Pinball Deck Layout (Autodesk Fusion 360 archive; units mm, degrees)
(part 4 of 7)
sketch "Round for Bumper" plane through (0, 0, 0) normal (0, 0, 1) x axis (1, 0, 0)
  line L1 (-43.2741, 196.0353) -> (-42.4787, 196.3248)
  line L2 (-43.527, 195.4929) -> (-43.2741, 196.0353)
  line L3 (-42.9846, 195.2399) -> (-43.527, 195.4929)
  line L4 (-42.1892, 195.5294) -> (-42.9846, 195.2399)
  line L5 (-43.0928, 194.2998) -> (-43.2375, 194.6975)
  line L6 (-43.1652, 194.4987) -> (-43.0928, 194.2998)
  line L7 (-41.9721, 194.9329) -> (-43.1652, 194.4987)
  line L8 (-42.2433, 195.0594) -> (-41.9721, 194.9329)
  line L9 (-42.6768, 193.7757) -> (-42.8757, 193.7033)
  line L10 (-42.6045, 193.5769) -> (-42.6768, 193.7757)
  line L11 (-42.8033, 193.5045) -> (-42.6045, 193.5769)
  line L12 (-42.8757, 193.7033) -> (-42.8033, 193.5045)
  line L13 (-41.2484, 192.9445) -> (-41.5196, 193.071)
  line L14 (-41.1037, 192.5469) -> (-41.2484, 192.9445)
  line L15 (-41.2302, 192.2757) -> (-41.1037, 192.5469)
  line L16 (-42.0255, 191.9862) -> (-41.2302, 192.2757)
  line L17 (-42.2967, 192.1126) -> (-42.0255, 191.9862)
  line L18 (-42.4414, 192.5103) -> (-42.2967, 192.1126)
  line L19 (-42.315, 192.7815) -> (-42.4414, 192.5103)
  line L20 (-41.5196, 193.071) -> (-42.315, 192.7815)
  line L21 (-40.5598, 196.8205) -> (-40.6863, 196.5493)
  line L22 (-40.7046, 197.2181) -> (-40.5598, 196.8205)
  line L23 (-40.9758, 197.3446) -> (-40.7046, 197.2181)
  line L24 (-41.7711, 197.0551) -> (-40.9758, 197.3446)
  line L25 (-41.8976, 196.7839) -> (-41.7711, 197.0551)
  line L26 (-41.7528, 196.3862) -> (-41.8976, 196.7839)
  line L27 (-41.4816, 196.2598) -> (-41.7528, 196.3862)
  line L28 (-41.391, 195.3921) -> (-41.5357, 195.7897)
  line L29 (-41.4634, 195.5909) -> (-41.391, 195.3921)
  line L30 (-40.668, 195.8804) -> (-41.4634, 195.5909)
  line L31 (-40.7404, 196.0792) -> (-40.668, 195.8804)
  line L32 (-41.1739, 194.7955) -> (-40.3785, 195.085)
  line L33 (-40.7762, 194.9403) -> (-41.1739, 194.7955)
  line L34 (-40.505, 194.8138) -> (-40.7762, 194.9403)
  line L35 (-40.2338, 194.6873) -> (-40.505, 194.8138)
  line L36 (-40.1614, 194.4885) -> (-40.2338, 194.6873)
  line L37 (-39.8719, 193.6932) -> (-39.6548, 193.0967)
  line L38 (-40.1431, 193.8196) -> (-39.8719, 193.6932)
  line L39 (-40.5408, 193.6749) -> (-40.1431, 193.8196)
  line L40 (-40.6673, 193.4037) -> (-40.5408, 193.6749)
  line L41 (-40.4502, 192.8072) -> (-40.6673, 193.4037)
  line L42 (-40.1607, 192.0118) -> (-40.3054, 192.4095)
  line L43 (-40.2331, 192.2107) -> (-40.1607, 192.0118)
  line L44 (-39.04, 192.6449) -> (-40.2331, 192.2107)
  line L45 (-39.1124, 192.8437) -> (-39.04, 192.6449)
  line L46 (-39.8712, 191.2165) -> (-39.7265, 190.8188)
  line L47 (-39.7447, 191.4877) -> (-39.8712, 191.2165)
  line L48 (-39.3471, 191.6324) -> (-39.7447, 191.4877)
  line L49 (-39.0758, 191.506) -> (-39.3471, 191.6324)
  line L50 (-38.9311, 191.1083) -> (-39.0758, 191.506)
  line L51 (-39.0576, 190.8371) -> (-38.9311, 191.1083)
  line L52 (-39.2564, 190.7647) -> (-39.0576, 190.8371)
  line L53 (-39.5459, 191.5601) -> (-39.2564, 190.7647)
  line L54 (-39.0751, 189.0293) -> (-37.8821, 189.4635)
  line L55 (-38.7856, 188.2339) -> (-39.0751, 189.0293)
  line L56 (-37.4479, 188.2705) -> (-37.1584, 187.4751)
  line L57 (-38.6409, 187.8362) -> (-37.4479, 188.2705)
  line L58 (-38.3514, 187.0409) -> (-38.6409, 187.8362)
  line L59 (-37.8996, 187.6557) -> (-38.0444, 188.0534)
  line L60 (-38.2067, 186.6432) -> (-37.0136, 187.0774)
  line L61 (-37.9896, 186.0467) -> (-38.2067, 186.6432)
  line L62 (-37.7184, 185.9202) -> (-37.9896, 186.0467)
  line L63 (-36.923, 186.2097) -> (-37.7184, 185.9202)
  line L64 (-36.7965, 186.4809) -> (-36.923, 186.2097)
  line L65 (-37.0136, 187.0774) -> (-36.7965, 186.4809)
  line L66 (-36.3623, 185.2879) -> (-36.4888, 185.0167)
  line L67 (-36.5071, 185.6856) -> (-36.3623, 185.2879)
  line L68 (-36.7783, 185.812) -> (-36.5071, 185.6856)
  line L69 (-36.9771, 185.7397) -> (-36.7783, 185.812)
  line L70 (-37.1036, 185.4685) -> (-36.9771, 185.7397)
  line L71 (-36.9588, 185.0708) -> (-37.1036, 185.4685)
  line L72 (-37.0853, 184.7996) -> (-36.9588, 185.0708)
  line L73 (-37.2841, 184.7272) -> (-37.0853, 184.7996)
  line L74 (-37.5553, 184.8537) -> (-37.2841, 184.7272)
  line L75 (-37.7001, 185.2514) -> (-37.5553, 184.8537)
  line L76 (-37.5736, 185.5226) -> (-37.7001, 185.2514)
  line L77 (-38.746, 198.1847) -> (-40.1776, 197.6636)
  line L78 (-38.4855, 197.4688) -> (-38.746, 198.1847)
  line L79 (-38.6372, 197.1434) -> (-38.4855, 197.4688)
  line L80 (-39.1144, 196.9697) -> (-38.6372, 197.1434)
  line L81 (-39.4399, 197.1215) -> (-39.1144, 196.9697)
  line L82 (-39.7004, 197.8373) -> (-39.4399, 197.1215)
  line L83 (-39.4829, 195.7548) -> (-39.6566, 196.232)
  line L84 (-39.5697, 195.9934) -> (-39.4829, 195.7548)
  line L85 (-38.6153, 196.3407) -> (-39.5697, 195.9934)
  line L86 (-38.7022, 196.5793) -> (-38.6153, 196.3407)
  line L87 (-38.2679, 195.3863) -> (-39.2223, 195.0389)
  line L88 (-38.0074, 194.6705) -> (-38.2679, 195.3863)
  line L89 (-38.1592, 194.3451) -> (-38.0074, 194.6705)
  line L90 (-38.875, 194.0845) -> (-38.1592, 194.3451)
  line L91 (-38.7013, 193.6073) -> (-37.2697, 194.1284)
  line L92 (-38.4407, 192.8915) -> (-38.7013, 193.6073)
  line L93 (-38.1153, 192.7397) -> (-38.4407, 192.8915)
  line L94 (-37.8767, 192.8266) -> (-38.1153, 192.7397)
  line L95 (-37.6381, 192.9134) -> (-37.8767, 192.8266)
  line L96 (-37.4863, 193.2389) -> (-37.6381, 192.9134)
  line L97 (-37.7469, 193.9547) -> (-37.4863, 193.2389)
  line L98 (-36.9653, 191.8072) -> (-37.1389, 192.2845)
  line L99 (-37.117, 191.4818) -> (-36.9653, 191.8072)
  line L100 (-37.8328, 191.2213) -> (-37.117, 191.4818)
  line L101 (-38.0934, 191.9371) -> (-37.8328, 191.2213)
  line L102 (-37.9416, 192.2625) -> (-38.0934, 191.9371)
  line L103 (-37.6162, 192.1108) -> (-37.9416, 192.2625)
  line L104 (-37.3556, 191.395) -> (-37.6162, 192.1108)
  line L105 (-37.4854, 190.2668) -> (-37.6591, 190.7441)
  line L106 (-37.5723, 190.5054) -> (-37.4854, 190.2668)
  line L107 (-36.1407, 191.0265) -> (-37.5723, 190.5054)
  line L108 (-36.2275, 191.2651) -> (-36.1407, 191.0265)
  line L109 (-37.0512, 189.0738) -> (-37.2249, 189.551)
  line L110 (-37.1381, 189.3124) -> (-37.0512, 189.0738)
  line L111 (-35.7064, 189.8335) -> (-37.1381, 189.3124)
  line L112 (-35.7933, 190.0721) -> (-35.7064, 189.8335)
  line L113 (-36.6059, 198.5102) -> (-36.7576, 198.1848)
  line L114 (-36.7796, 198.9875) -> (-36.6059, 198.5102)
  line L115 (-37.105, 199.1392) -> (-36.7796, 198.9875)
  line L116 (-37.3436, 199.0524) -> (-37.105, 199.1392)
  line L117 (-37.4954, 198.7269) -> (-37.3436, 199.0524)
  line L118 (-37.3217, 198.2497) -> (-37.4954, 198.7269)
  line L119 (-37.4735, 197.9243) -> (-37.3217, 198.2497)
  line L120 (-37.7121, 197.8374) -> (-37.4735, 197.9243)
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sketch "Sketch43" plane through (0, 0, 0) normal (0, 0, 1) x axis (1, 0, 0)
sketch "Speaker Grille" plane through (0, 0, 0) normal (0, 0, 1) x axis (1, 0, 0)
  circle C1 centre (2212.5, 1932.5) radius 45
  circle C2 centre (2212.5, 1932.5) radius 67.5
  circle C3 centre (2171.5, 1973.5) radius 6
  circle C4 centre (2253.5, 1973.5) radius 6
  circle C5 centre (2253.5, 1891.5) radius 6
  circle C6 centre (2171.5, 1891.5) radius 6
  circle C7 centre (2648.5, 1973.5) radius 6
  circle C8 centre (2566.5, 1973.5) radius 6
  circle C9 centre (2607.5, 1932.5) radius 45
  circle C10 centre (2607.5, 1932.5) radius 67.5
  circle C11 centre (2648.5, 1891.5) radius 6
  circle C12 centre (2566.5, 1891.5) radius 6
  point P2 (2212.5, 1932.5)
  point P3 (2212.5, 1932.5)
  point P5 (2171.5, 1973.5)
  point P6 (2171.5, 1973.5)
  coincident P2 P3
  concentric C1 C2
  coincident P5 P6
  concentric C9 C10
extrude "Extrude174" new body sketch "Speaker Grille" profile of C1 C2 C3 C4 C5 C6 along normal blind 8 bodies "Speaker Grille"
extrude "Extrude175" add sketch "Speaker Grille" profile of C3 C4 C5 C6 blind 3 from offset 5
extrude "Extrude176" add sketch "Speaker Grille" profile of C1 blind 3 from offset 5
sketch "Speaker Grille Holes" plane through (0, 0, 8) normal (0, 0, 1) x axis (-1, 0, 0)
  circle C1 centre (-2212.5, -1932.5) radius 67.5
  circle C2 centre (-2212.5, -1932.5) radius 4
  circle C3 centre (-2212.5, -1944.5) radius 4
  circle C4 centre (-2202.1077, -1938.5) radius 4
  circle C5 centre (-2202.1077, -1926.5) radius 4
  circle C6 centre (-2212.5, -1920.5) radius 4
  circle C7 centre (-2222.8923, -1926.5) radius 4
  circle C8 centre (-2222.8923, -1938.5) radius 4
  circle C9 centre (-2212.5, -1956.5) radius 4
  circle C10 centre (-2200.5, -1953.2846) radius 4
  circle C11 centre (-2191.7154, -1944.5) radius 4
  circle C12 centre (-2188.5, -1932.5) radius 4
  circle C13 centre (-2191.7154, -1920.5) radius 4
  circle C14 centre (-2200.5, -1911.7154) radius 4
  circle C15 centre (-2212.5, -1908.5) radius 4
  circle C16 centre (-2224.5, -1911.7154) radius 4
  circle C17 centre (-2233.2846, -1920.5) radius 4
  circle C18 centre (-2236.5, -1932.5) radius 4
  circle C19 centre (-2233.2846, -1944.5) radius 4
  circle C20 centre (-2224.5, -1953.2846) radius 4
  circle C21 centre (-2212.5, -1968.5) radius 4
  circle C22 centre (-2200.1873, -1966.3289) radius 4
  circle C23 centre (-2189.3596, -1960.0776) radius 4
  circle C24 centre (-2181.3231, -1950.5) radius 4
  circle C25 centre (-2177.0469, -1938.7513) radius 4
  circle C26 centre (-2177.0469, -1926.2487) radius 4
  circle C27 centre (-2181.3231, -1914.5) radius 4
  circle C28 centre (-2189.3596, -1904.9224) radius 4
  circle C29 centre (-2200.1873, -1898.6711) radius 4
  circle C30 centre (-2212.5, -1896.5) radius 4
  circle C31 centre (-2224.8127, -1898.6711) radius 4
  circle C32 centre (-2235.6404, -1904.9224) radius 4
  circle C33 centre (-2243.6769, -1914.5) radius 4
  circle C34 centre (-2247.9531, -1926.2487) radius 4
  circle C35 centre (-2247.9531, -1938.7513) radius 4
  circle C36 centre (-2243.6769, -1950.5) radius 4
  circle C37 centre (-2235.6404, -1960.0776) radius 4
  circle C38 centre (-2224.8127, -1966.3289) radius 4
  circle C39 centre (-2212.5, -1980.5) radius 4
  circle C40 centre (-2200.0767, -1978.8644) radius 4
  circle C41 centre (-2188.5, -1974.0692) radius 4
  circle C42 centre (-2170.9308, -1956.5) radius 4
  circle C43 centre (-2166.1356, -1944.9233) radius 4
  circle C44 centre (-2164.5, -1932.5) radius 4
  circle C45 centre (-2166.1356, -1920.0767) radius 4
  circle C46 centre (-2170.9308, -1908.5) radius 4
  circle C47 centre (-2188.5, -1890.9308) radius 4
  circle C48 centre (-2200.0767, -1886.1356) radius 4
  circle C49 centre (-2212.5, -1884.5) radius 4
  circle C50 centre (-2224.9233, -1886.1356) radius 4
  circle C51 centre (-2236.5, -1890.9308) radius 4
  circle C52 centre (-2254.0692, -1908.5) radius 4
  circle C53 centre (-2258.8644, -1920.0767) radius 4
  circle C54 centre (-2260.5, -1932.5) radius 4
  circle C55 centre (-2258.8644, -1944.9233) radius 4
  circle C56 centre (-2254.0692, -1956.5) radius 4
  circle C57 centre (-2236.5, -1974.0692) radius 4
  circle C58 centre (-2224.9233, -1978.8644) radius 4
  circle C59 centre (-2272.5, -1932.5) radius 5
  circle C60 centre (-2272.5, -1932.5) radius 2.4
  circle C61 centre (-2212.5, -1992.5) radius 2.4
  circle C62 centre (-2212.5, -1992.5) radius 5
  circle C63 centre (-2152.5, -1932.5) radius 2.4
  circle C64 centre (-2152.5, -1932.5) radius 5
  circle C65 centre (-2212.5, -1872.5) radius 2.4
  circle C66 centre (-2212.5, -1872.5) radius 5
  arc A1 centre (-2212.5, -1932.5) radius 53 clockwise from (-2161.3349, -1946.3252) to (-2198.8813, -1983.7204)
  arc A2 centre (-2212.5, -1932.5) radius 53 clockwise from (-2226.7387, -1983.5515) to (-2263.6765, -1946.2829)
  arc A3 centre (-2212.5, -1932.5) radius 53 clockwise from (-2198.8356, -1881.2918) to (-2161.4158, -1918.3788)
  arc A4 centre (-2212.5, -1932.5) radius 53 clockwise from (-2263.5966, -1918.424) to (-2226.2846, -1881.324)
  arc A5 centre (-2607.5, -1932.5) radius 53 clockwise from (-2658.5966, -1918.424) to (-2621.2846, -1881.324)
  arc A6 centre (-2607.5, -1932.5) radius 53 clockwise from (-2621.7387, -1983.5515) to (-2658.6765, -1946.2829)
  arc A7 centre (-2607.5, -1932.5) radius 53 clockwise from (-2556.3349, -1946.3252) to (-2593.8813, -1983.7204)
  arc A8 centre (-2607.5, -1932.5) radius 53 clockwise from (-2593.8356, -1881.2918) to (-2556.4158, -1918.3788)
  circle C67 centre (-2607.5, -1992.5) radius 5
  circle C68 centre (-2607.5, -1992.5) radius 2.4
  circle C69 centre (-2547.5, -1932.5) radius 2.4
  circle C70 centre (-2547.5, -1932.5) radius 5
  circle C71 centre (-2607.5, -1872.5) radius 2.4
  circle C72 centre (-2607.5, -1872.5) radius 5
  circle C73 centre (-2667.5, -1932.5) radius 2.4
  circle C74 centre (-2667.5, -1932.5) radius 5
  point P3 (-2212.5, -1932.5)
  point P68 (-2212.5, -1932.5)
  point P71 (-2212.5, -1932.5)
  point P74 (-2212.5, -1932.5)
  point P77 (-2212.5, -1932.5)
  point P80 (-2607.5, -1932.5)
  point P91 (-2607.5, -1932.5)
  concentric C1 C2
  concentric C59 C60
  coincident P3 P68
  coincident P3 P71
  coincident P3 P74
  coincident P68 P77
  coincident P80 P91
  dimension "d1064" radius A1 = 53
  dimension "d1065" radius A2 = 53
  dimension "d1070" radius A3 = 53
  dimension "d1071" radius A4 = 53
  dimension "d1114" radius A7 = 53
  dimension "d1115" radius A6 = 53
  dimension "d1116" radius A8 = 53
  dimension "d1117" radius A5 = 53
  dimension "d1048" C-Pattern1-Angle = 360
  dimension "d1050" C-Pattern2-Angle = 360
  dimension "d1052" C-Pattern3-Angle = 360
  dimension "d1054" C-Pattern4-Angle = 360
  dimension "d1058" C-Pattern5-Angle = 360
  dimension "d1066" Text1-Height = 10
  dimension "d1068" Text2-Height = 10
  dimension "d1072" Text3-Height = 10
  dimension "d1074" Text4-Height = 10
  dimension "d1106" Text5-Height = 10
  dimension "d1108" Text6-Height = 10
  dimension "d1110" Text7-Height = 10
  dimension "d1112" Text8-Height = 10
  dimension "d1119" C-Pattern6-Angle = 360
extrude "Extrude177" cut sketch "Speaker Grille Holes" profile of C2 C3 C4 C5 C6 C7 C8 C9 C10 C11 C12 C13 C14 C15 C16 C17 C18 C19 C20 C21 C22 C23 C24 C25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 against normal blind 20
extrude "Extrude178" cut sketch "Speaker Grille Holes" profile of C59 C60 C61 C62 C63 C64 C65 C66 against normal blind 5
chamfer "Chamfer16" distance 2
extrude "Extrude179" cut sketch "Speaker Grille Holes" against normal blind 0.6
extrude "Extrude184" new body sketch "Speaker Grille" profile of C7 C8 C9 C10 C11 C12 along normal blind 8 bodies "Speaker Grille Transistor"
extrude "Extrude185" add sketch "Speaker Grille" profile of C7 C8 C11 C12 blind 3 from offset 5
extrude "Extrude186" add sketch "BackBox" blind 5 from offset 3
extrude "Extrude187" cut sketch "Speaker Grille Holes" profile of C67 C68 C69 C70 C71 C72 C73 C74 against normal blind 5
extrude "Extrude188" cut sketch "Speaker Grille Holes" profile of C68 C69 C71 C73 against normal blind 20
extrude "Extrude189" cut sketch "Speaker Grille Holes" against normal blind 1
chamfer "Chamfer19" distance 1 distance 2
chamfer "Chamfer20" distance 2.5 distance 2.5
extrude "Extrude190" new body sketch "BackBox" along normal blind 1.6 bodies "Score and Player Stencil"
extrude "Extrude192" cut sketch "BackBox" along normal blind 10 bodies "Score and Player Stencil (1)", "Score and Player Stencil (2)", "Score and Player Stencil (3)", "Score and Player Stencil (4)", "Score and Player Stencil (5)"
extrude "Extrude193" add sketch "BackBox" along normal blind 1.6 bodies "Score and Player Stencil (1)", "Score and Player Stencil (2)", "Score and Player Stencil (3)", "Score and Player Stencil (4)", "Score and Player Stencil (5)"
sketch "TGM" plane through (0, 0, 26.8) normal (0, 0, 1) x axis (-1, 0, 0)
  curve K1 (-394.895, -516.8116) -> (-148.3535, -405.68)
  curve K2 (-362.2071, -513.1144) -> (-394.895, -516.8116)
  curve K3 (-392.0081, -507.9705) -> (-362.2071, -513.1144)
  curve K4 (-148.3535, -405.68) -> (-392.0081, -507.9705)
  line L1 (-352.5662, -523.8611) -> (-337.4773, -506.6421)
  line L2 (-356.4045, -516.3957) -> (-333.6368, -513.9907)
  line L3 (-352.3287, -506.4533) -> (-337.4165, -523.8216)
  line L4 (-345.8439, -503.8414) -> (-344.2038, -526.6773)
  curve K5 (-332.1435, -465.5509) -> (-304.0612, -510.3266)
  curve K6 (-304.0643, -503.1407) -> (-304.0581, -517.5125)
  curve K7 (-337.0307, -462.8305) -> (-327.2563, -468.2714)
  curve K8 (-328.9554, -457.7991) -> (-296.2565, -506.0172)
  curve K9 (-296.4222, -499.7021) -> (-296.0909, -512.3322)
  curve K10 (-334.5203, -454.8035) -> (-323.3905, -460.7946)
  curve K11 (-258.096, -394.5655) -> (-256.0404, -399.4978)
  curve K12 (-260.096, -394.5655) -> (-258.096, -394.5655)
  curve K13 (-262.096, -398.5655) -> (-260.096, -394.5655)
  curve K14 (-253.3716, -424.5776) -> (-256.0404, -399.4978)
  curve K15 (-265.3252, -424.1348) -> (-262.096, -398.5655)
  curve K16 (-286.9785, -407.2003) -> (-287.0771, -401.8711)
  curve K17 (-287.0771, -401.8711) -> (-282.6123, -402.0668)
  curve K18 (-282.6123, -402.0668) -> (-280.7826, -407.4713)
  curve K19 (-285.577, -415.4972) -> (-286.9785, -407.2003)
  curve K20 (-285.1672, -416.3355) -> (-285.9868, -414.6589)
  curve K21 (-332.7729, -448.7758) -> (-307.0356, -466.5006)
  curve K22 (-337.6691, -448.7758) -> (-332.7729, -448.7758)
  curve K23 (-336.4498, -444.5132) -> (-337.6691, -448.7758)
  curve K24 (-332, -445) -> (-336.4498, -444.5132)
  curve K25 (-298.7139, -460.4547) -> (-332, -445)
  curve K26 (-358.1837, -553.1493) -> (-358.3367, -550.0237)
  curve K27 (-359.8524, -555.6804) -> (-358.1837, -553.1493)
  curve K28 (-362.1811, -556.7129) -> (-359.8524, -555.6804)
  curve K29 (-365.399, -556.1322) -> (-362.1811, -556.7129)
  curve K30 (-367.832, -552.7289) -> (-365.399, -556.1322)
  curve K31 (-367.6403, -550.1846) -> (-367.832, -552.7289)
  curve K32 (-361.124, -547.211) -> (-358.4275, -549.8052)
  curve K33 (-354.3728, -543.4851) -> (-352.3173, -537.9664)
  curve K34 (-355.3735, -545.8038) -> (-353.3722, -541.1663)
  curve K35 (-358.3367, -550.0237) -> (-358.0882, -549.7182)
  curve K36 (-358.1133, -549.7497) -> (-358.063, -549.6868)
  curve K37 (-358.3624, -550.0547) -> (-358.3111, -549.9927)
  curve K38 (-358.6852, -542.9275) -> (-360.6858, -533.0429)
  curve K39 (-359.4374, -545.1004) -> (-357.9329, -540.7546)
  curve K40 (-365.2949, -547.4437) -> (-361.7976, -546.9968)
  curve K41 (-365.2949, -547.4437) -> (-367.6403, -550.1846)
  curve K42 (-338.3016, -546.0245) -> (-340.647, -548.7654)
  curve K43 (-331.3434, -548.6045) -> (-331.0949, -548.2991)
  curve K44 (-331.12, -548.3305) -> (-331.0697, -548.2676)
  curve K45 (-331.3691, -548.6355) -> (-331.3178, -548.5735)
  curve K46 (-335.1878, -555.2938) -> (-332.8591, -554.2612)
  curve K47 (-338.3016, -546.0245) -> (-334.8043, -545.5776)
  curve K48 (-327.3795, -542.0659) -> (-328.5961, -518.8979)
  curve K49 (-328.3802, -544.3846) -> (-326.3789, -539.7472)
  curve K50 (-332.8591, -554.2612) -> (-331.1904, -551.7302)
  curve K51 (-338.4057, -554.7131) -> (-335.1878, -555.2938)
  curve K52 (-334.1307, -545.7918) -> (-331.4342, -548.386)
  curve K53 (-331.6919, -541.5084) -> (-332.9354, -521.61)
  curve K54 (-332.4441, -543.6812) -> (-330.9396, -539.3355)
  curve K55 (-340.647, -548.7654) -> (-340.8386, -551.3097)
  curve K56 (-331.1904, -551.7302) -> (-331.3434, -548.6045)
  curve K57 (-340.8386, -551.3097) -> (-338.4057, -554.7131)
  curve K58 (-397.0602, -517.7138) -> (-144.7627, -402.5381)
  curve K59 (-368.4267, -511.372) -> (-397.0602, -517.7138)
  curve K60 (-395, -510) -> (-368.4267, -511.372)
  curve K61 (-144.7627, -402.5381) -> (-395, -510)
  curve K62 (-320.1132, -535.4659) -> (-160.9431, -423.5396)
  curve K63 (-277.7807, -414.9917) -> (-280.7826, -407.4713)
  curve K64 (-277.6152, -415.8774) -> (-277.9462, -414.1061)
  line L5 (-298.7139, -460.4547) -> (-307.0356, -466.5006)
  line L6 (-265.3252, -424.1348) -> (-253.3716, -424.5776)
  line L7 (-332.9354, -521.61) -> (-328.5961, -518.8979)
  line L8 (-243.986, -236.4878) -> (-243.986, -233.4398)
  line L9 (-284.626, -327.9278) -> (-284.626, -324.8798)
  line L10 (-264.306, -327.9278) -> (-264.306, -324.8798)
  line L11 (-243.986, -327.9278) -> (-243.986, -324.8798)
  line L12 (-223.666, -327.9278) -> (-223.666, -324.8798)
  line L13 (-203.346, -327.9278) -> (-203.346, -324.8798)
  line L14 (-233.826, -305.0678) -> (-233.826, -302.0198)
  line L15 (-213.506, -305.0678) -> (-213.506, -302.0198)
  line L16 (-264.306, -282.2078) -> (-264.306, -279.1598)
  line L17 (-243.986, -282.2078) -> (-243.986, -279.1598)
  line L18 (-223.666, -282.2078) -> (-223.666, -279.1598)
  line L19 (-254.146, -259.3478) -> (-254.146, -256.2998)
  line L20 (-233.826, -259.3478) -> (-233.826, -256.2998)
  line L21 (-274.466, -305.0678) -> (-274.466, -302.0198)
  line L22 (-254.146, -305.0678) -> (-254.146, -302.0198)
  line L23 (-223.666, -327.9278) -> (-223.666, -324.8798)
  line L24 (-203.346, -327.9278) -> (-203.346, -324.8798)
  line L25 (-264.306, -327.9278) -> (-264.306, -324.8798)
  line L26 (-264.306, -282.2078) -> (-264.306, -279.1598)
  line L27 (-284.626, -327.9278) -> (-284.626, -324.8798)
  line L28 (-243.986, -236.4878) -> (-243.986, -233.4398)
  line L29 (-254.146, -259.3478) -> (-254.146, -256.2998)
  line L30 (-254.146, -305.0678) -> (-254.146, -302.0198)
  line L31 (-233.826, -259.3478) -> (-233.826, -256.2998)
  line L32 (-274.466, -305.0678) -> (-274.466, -302.0198)
  line L33 (-223.666, -282.2078) -> (-223.666, -279.1598)
  line L34 (-243.986, -282.2078) -> (-243.986, -279.1598)
  line L35 (-213.506, -305.0678) -> (-213.506, -302.0198)
  line L36 (-233.826, -305.0678) -> (-233.826, -302.0198)
  line L37 (-243.986, -327.9278) -> (-243.986, -324.8798)
  line L38 (-223.666, -327.9278) -> (-223.666, -324.8798)
  line L39 (-203.346, -327.9278) -> (-203.346, -324.8798)
  line L40 (-264.306, -327.9278) -> (-264.306, -324.8798)
  line L41 (-264.306, -282.2078) -> (-264.306, -279.1598)
  line L42 (-284.626, -327.9278) -> (-284.626, -324.8798)
  line L43 (-243.986, -236.4878) -> (-243.986, -233.4398)
  line L44 (-254.146, -259.3478) -> (-254.146, -256.2998)
  line L45 (-254.146, -305.0678) -> (-254.146, -302.0198)
  line L46 (-233.826, -259.3478) -> (-233.826, -256.2998)
  line L47 (-274.466, -305.0678) -> (-274.466, -302.0198)
  line L48 (-223.666, -282.2078) -> (-223.666, -279.1598)
  line L49 (-243.986, -282.2078) -> (-243.986, -279.1598)
  line L50 (-213.506, -305.0678) -> (-213.506, -302.0198)
  line L51 (-233.826, -305.0678) -> (-233.826, -302.0198)
  line L52 (-243.986, -327.9278) -> (-243.986, -324.8798)
  circle C1 centre (-345.0137, -515.2586) radius 11.4474
  circle C2 centre (-362.9589, -551.8166) radius 4.9577
  circle C3 centre (-335.9656, -550.3974) radius 4.9577
  arc A1 centre (-243.986, -233.4398) radius 0.0635 clockwise from (-244.0495, -233.4398) to (-243.9225, -233.4398)
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  point P43 (-352.5662, -523.8611)
  point P44 (-356.4045, -516.3957)
  point P45 (-352.3287, -506.4533)
  point P46 (-337.4773, -506.6421)
  point P47 (-333.6368, -513.9907)
  point P48 (-337.4165, -523.8216)
  point P49 (-344.2038, -526.6773)
  point P50 (-345.8439, -503.8414)
  point P54 (-304.0612, -510.3266)
  point P55 (-332.1435, -465.5509)
  point P65 (-328.9554, -457.7991)
  point P66 (-296.2565, -506.0172)
  point P119 (-285.577, -415.4972)
  point P151 (-360.6858, -533.0429)
  point P153 (-352.3173, -537.9664)
  point P157 (-358.3367, -550.0237)
  point P163 (-358.1837, -553.1493)
  point P171 (-359.8524, -555.6804)
  point P179 (-362.1811, -556.7129)
  point P188 (-365.399, -556.1322)
  point P194 (-367.832, -552.7289)
  point P201 (-367.6403, -550.1846)
  point P202 (-358.4275, -549.8052)
  point P208 (-361.124, -547.211)
  point P209 (-354.3728, -543.4851)
  point P212 (-358.0882, -549.7182)
  point P217 (-358.6852, -542.9275)
  point P220 (-361.7976, -546.9968)
  point P227 (-365.2949, -547.4437)
  point P253 (-331.3434, -548.6045)
  point P282 (-331.1904, -551.7302)
  point P255 (-332.8591, -554.2612)
  point P305 (-335.1878, -555.2938)
  point P269 (-338.4057, -554.7131)
  point P251 (-340.8386, -551.3097)
  point P291 (-340.647, -548.7654)
  point P241 (-331.4342, -548.386)
  point P308 (-334.1307, -545.7918)
  point P234 (-327.3795, -542.0659)
  point P236 (-331.0949, -548.2991)
  point P284 (-331.6919, -541.5084)
  point P311 (-334.8043, -545.5776)
  point P312 (-338.3016, -546.0245)
  point P365 (-277.7807, -414.9917)
  point P95 (-262.9776, -416.5536)
  point P60 (-296.4222, -499.7021)
  point P68 (-296.4222, -499.7021)
  point P56 (-304.0581, -517.5125)
  point P362 (-304.0581, -517.5125)
  point P92 (-254.6103, -418.8368)
  coincident C1 P43
  coincident C1 P44
  coincident C1 P45
  coincident C1 P46
  coincident C1 P47
  coincident C1 P48
  coincident C1 P49
  coincident C1 P50
  coincident K1 P54
  coincident K4 P55
  midpoint P54 K6
  midpoint P55 K7
  coincident K4 P65
  coincident K1 P66
  midpoint P66 K9
  midpoint P65 K10
  coincident K4 P119
  midpoint P119 K20
  coincident K1 P151
  coincident K1 P153
  coincident C2 P157
  coincident C2 P163
  coincident C2 P171
  coincident C2 P179
  coincident C2 P188
  coincident C2 P194
  coincident C2 P201
  coincident C2 P202
  coincident C2 P208
  coincident K32 P209
  midpoint P209 K34
  coincident K32 P212
  midpoint P212 K36
  midpoint P157 K37
  coincident K32 P217
  midpoint P217 K39
  coincident C2 P220
  coincident C2 P227
  coincident P253 C3
  coincident P282 C3
  coincident P255 C3
  coincident P305 C3
  coincident P269 C3
  coincident P251 C3
  coincident P291 C3
  coincident P241 C3
  coincident P308 C3
  coincident P234 K52
  midpoint P234 K49
  coincident P236 K52
  midpoint P236 K44
  midpoint P253 K45
  coincident P284 K52
  midpoint P284 K54
  coincident P311 C3
  coincident P312 C3
  coincident K4 P365
  midpoint P365 K64
  coincident K4 P95
  coincident P60 P68
  coincident P56 P362
  coincident K4 P92
  dimension "d1224" diameter = 12
  dimension "d1225" diameter = 12
  dimension "d1139" Text1-Height = 8
  dimension "d1141" Text2-Height = 8
sketch "Sketch48" plane through (0, 0, 0) normal (0, 0, 1) x axis (1, 0, 0)
sketch "TGM Stencil Outline" plane through (0, 0, 26.8) normal (0, 0, 1) x axis (-1, 0, 0)
  line L1 (-335.7762, -328.4574) -> (-138.9755, -401.734)
  line L2 (-212.252, -598.5347) -> (-138.9755, -401.734)
  line L3 (-409.0528, -525.2582) -> (-212.252, -598.5347)
  line L4 (-409.0528, -525.2582) -> (-335.7762, -328.4574)
  line L5 (-235, -435) -> (-235, -375)
  line L6 (-300, -435) -> (-235, -435)
  line L7 (-300, -375) -> (-300, -435)
  line L8 (-235, -375) -> (-300, -375)
  line L9 (-290, -435) -> (-290, -513.0916)
  line L10 (-350, -435) -> (-290, -435)
  line L11 (-350, -513.0916) -> (-350, -435)
  line L12 (-290, -513.0916) -> (-350, -513.0916)
  line L13 (-380, -570) -> (-320, -570)
  line L14 (-380, -515) -> (-380, -570)
  line L15 (-320, -515) -> (-380, -515)
  line L16 (-320, -570) -> (-320, -515)
  line L17 (-360, -530) -> (-360, -500)
  line L18 (-330, -530) -> (-360, -530)
  line L19 (-330, -500) -> (-330, -530)
  line L20 (-360, -500) -> (-330, -500)
  point P11 (-290, -435)
  point P2 (-138.9755, -401.734)
  point P3 (-335.7762, -328.4574)
  point P4 (-212.252, -598.5347)
  point P5 (-409.0528, -525.2582)
  perpendicular L1 L2
  perpendicular L2 L3
  vertical L5
  perpendicular L5 L6
  perpendicular L6 L7
  perpendicular L5 L8
  coincident L6 P11
  perpendicular L6 L9
  perpendicular L9 L10
  perpendicular L10 L11
  perpendicular L9 L12
  parallel L12 L13
  perpendicular L12 L14
  perpendicular L14 L15
  perpendicular L13 L16
  vertical L17
  perpendicular L17 L18
  perpendicular L18 L19
  perpendicular L17 L20
  dimension "d1161" distance P2 P3 = 210
  dimension "d1162" distance P2 P4 = 210
  dimension "d1163" distance P4 P5 = 210
extrude "Extrude201" new body sketch "TGM Stencil Outline" profile of L1 L2 L3 L4 along normal blind 1.4 bodies "TGM Body Outline"
extrude "Extrude202" cut sketch "TGM" profile of K1 K2 K3 K4 K14 K15 K19 K21 K25 K38 K35 K42 K47 K48 K53 K58 K59 K60 K61 K63 along normal blind 10
extrude "Extrude203" new body sketch "TGM Stencil Outline" profile of L1 L2 L3 L4 along normal blind 1.4 bodies "TGM Main Body"
extrude "Extrude205" cut sketch "TGM" profile of K1 K2 K3 K4 C1 L1 L2 L3 L4 K5 K8 K14 K15 K21 K25 K48 K53 L5 L6 L7 along normal blind 10
extrude "Extrude206" new body sketch "TGM Stencil Outline" profile of L5 L6 L7 L8 L10 along normal blind 1.6 bodies "TGM Legs"
extrude "Extrude207" cut sketch "TGM" profile of K4 K11 K12 K13 K14 K15 K16 K17 K18 K19 K61 K63 L6 along normal blind 10
extrude "Extrude208" new body sketch "TGM Stencil Outline" profile of L6 L9 L10 L11 L12 L19 L20 along normal blind 1.6 bodies "TGM Arms"
extrude "Extrude209" cut sketch "TGM" profile of K4 K21 K22 K23 K24 K25 K61 L5 along normal blind 10
extrude "Extrude210" new body sketch "TGM Stencil Outline" profile of L6 L9 L10 L11 L12 L19 L20 along normal blind 1.4 bodies "TGM Necklace"
extrude "Extrude211" cut sketch "TGM" profile of K1 K4 K5 K8 along normal blind 10
extrude "Extrude212" new body sketch "TGM Stencil Outline" profile of L6 L9 L10 L11 L12 L19 L20 along normal blind 1.4 bodies "TGM Necklace 2"
extrude "Extrude213" cut sketch "TGM" along normal blind 10
extrude "Extrude214" new body sketch "TGM" + "TGM Stencil Outline" profile of S1:K1 S1:C1 S1:L1 S1:L2 S1:L3 S1:L4 S1:K38 S1:K35 S1:C2 S1:K26 S1:K27 S1:K28 S1:K29 S1:K30 S1:K31 S1:K32 S1:K40 S1:K41 S1:K42 S1:C3 S1:K43 S1:K46 S1:K47 S1:K48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 blind 1.4 bodies "TGM Ears"
extrude "Extrude215" cut sketch "TGM" profile of C2 K26 K27 K28 K29 K30 K31 K32 K40 K41 K42 C3 K46 K47 K50 K51 K52 K55 K56 K57 K58 along normal blind 10
extrude "Extrude216" new body sketch "TGM" + "TGM Stencil Outline" profile of S1:K1 S1:C1 S1:L1 S1:L2 S1:L3 S1:L4 S1:K38 S1:K35 S1:C2 S1:K26 S1:K27 S1:K28 S1:K29 S1:K30 S1:K31 S1:K32 S1:K40 S1:K41 S1:K42 S1:C3 S1:K43 S1:K46 S1:K47 S1:K48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 blind 1.4 bodies "TGM Ears 2"
extrude "Extrude217" cut sketch "TGM" profile of K1 K38 K35 C2 K32 C3 K48 K52 K53 K58 L7 along normal blind 10
extrude "Extrude220" new body sketch "TGM Stencil Outline" profile of L11 L12 L15 L17 L18 L19 L20 along normal blind 1.4 bodies "TGM Eyes 2"
extrude "Extrude221" cut sketch "TGM" profile of C1 L1 L2 L3 L4 along normal blind 10
extrude "Extrude222" new body sketch "TGM Stencil Outline" profile of L11 L12 L15 L17 L18 L19 L20 along normal blind 1.4 bodies "TGM Eyes 3"
extrude "Extrude223" cut sketch "TGM" profile of C1 L1 L2 L3 L4 along normal blind 10
extrude "Extrude224" new body sketch "Front panel Plunger" profile of L1 C1 C2 C3 C4 C5 L3 L4 L5 L6 along normal blind 4 bodies "Launcher Shim - 6.6 degree"
chamfer "Chamfer21" distance 25 distance 2.8
sketch "Pinball Deck Cut and Drill" plane through (0, 0, 0) normal (0, 0, 1) x axis (1, 0, 0)
  line L1 (465, 645) -> (465, 532.1855)
  line L2 (465, 643) -> (443, 643)
  line L3 (465, 531) -> (465, 643)
  line L4 (443, 531) -> (465, 531)
  line L5 (443, 643) -> (443, 531)
  line L6 (287.9675, 328.1202) -> (287.9675, 325.0722)
  line L7 (247.3275, 328.1202) -> (247.3275, 325.0722)
  line L8 (227.0075, 328.1202) -> (227.0075, 325.0722)
  line L9 (287.9675, 328.1202) -> (287.9675, 325.0722)
  line L10 (206.6875, 328.1202) -> (206.6875, 325.0722)
  line L11 (227.0075, 328.1202) -> (227.0075, 325.0722)
  line L12 (227.0075, 328.1202) -> (227.0075, 325.0722)
  line L13 (247.3275, 236.6802) -> (247.3275, 233.6322)
  line L14 (247.3275, 236.6802) -> (247.3275, 233.6322)
  line L15 (267.6475, 328.1202) -> (267.6475, 325.0722)
  line L16 (237.1675, 259.5402) -> (237.1675, 256.4922)
  line L17 (216.8475, 305.2602) -> (216.8475, 302.2122)
  line L18 (247.3275, 236.6802) -> (247.3275, 233.6322)
  line L19 (237.1675, 259.5402) -> (237.1675, 256.4922)
  line L20 (227.0075, 282.4002) -> (227.0075, 279.3522)
  line L21 (227.0075, 282.4002) -> (227.0075, 279.3522)
  line L22 (247.3275, 282.4002) -> (247.3275, 279.3522)
  line L23 (247.3275, 282.4002) -> (247.3275, 279.3522)
  line L24 (247.3275, 282.4002) -> (247.3275, 279.3522)
  line L25 (216.8475, 305.2602) -> (216.8475, 302.2122)
  line L26 (216.8475, 305.2602) -> (216.8475, 302.2122)
  line L27 (237.1675, 259.5402) -> (237.1675, 256.4922)
  line L28 (227.0075, 282.4002) -> (227.0075, 279.3522)
  line L29 (287.9675, 328.1202) -> (287.9675, 325.0722)
  line L30 (206.6875, 328.1202) -> (206.6875, 325.0722)
  line L31 (247.3275, 328.1202) -> (247.3275, 325.0722)
  line L32 (267.6475, 328.1202) -> (267.6475, 325.0722)
  line L33 (267.6475, 328.1202) -> (267.6475, 325.0722)
  line L34 (247.3275, 328.1202) -> (247.3275, 325.0722)
  line L35 (206.6875, 328.1202) -> (206.6875, 325.0722)
  line L36 (257.4875, 259.5402) -> (257.4875, 256.4922)
  line L37 (267.6475, 282.4002) -> (267.6475, 279.3522)
  line L38 (267.6475, 282.4002) -> (267.6475, 279.3522)
  line L39 (257.4875, 259.5402) -> (257.4875, 256.4922)
  line L40 (267.6475, 282.4002) -> (267.6475, 279.3522)
  line L41 (257.4875, 305.2602) -> (257.4875, 302.2122)
  line L42 (257.4875, 259.5402) -> (257.4875, 256.4922)
  line L43 (257.4875, 305.2602) -> (257.4875, 302.2122)
  line L44 (257.4875, 305.2602) -> (257.4875, 302.2122)
  line L45 (237.1675, 305.2602) -> (237.1675, 302.2122)
  line L46 (237.1675, 305.2602) -> (237.1675, 302.2122)
  line L47 (237.1675, 305.2602) -> (237.1675, 302.2122)
  line L48 (277.8075, 305.2602) -> (277.8075, 302.2122)
  line L49 (277.8075, 305.2602) -> (277.8075, 302.2122)
  line L50 (277.8075, 305.2602) -> (277.8075, 302.2122)
  line L51 (75, 539) -> (75, 651)
  line L52 (97, 539) -> (75, 539)
  line L53 (97, 651) -> (97, 539)
  line L54 (75, 651) -> (97, 651)
  line L55 (396.5883, 324.0888) -> (374.357, 263.0087)
  line L56 (363.6058, 309.489) -> (358.4755, 295.3936)
  line L57 (374.357, 263.0087) -> (357.4425, 269.1651)
  line L58 (396.5883, 324.0888) -> (379.6738, 330.2451)
  line L59 (371.1233, 306.7528) -> (379.6738, 330.2451)
  line L60 (365.993, 292.6574) -> (357.4425, 269.1651)
  line L61 (358.4755, 295.3936) -> (365.993, 292.6574)
  line L62 (363.6058, 309.489) -> (371.1233, 306.7528)
  line L63 (136.4349, 309.489) -> (141.5652, 295.3936)
  line L64 (125.7627, 263.0375) -> (142.6772, 269.1939)
  line L65 (136.4349, 309.489) -> (128.9174, 306.7528)
  line L66 (128.9174, 306.7528) -> (120.3669, 330.2451)
  line L67 (141.5652, 295.3936) -> (134.1267, 292.6862)
  line L68 (103.5314, 324.1175) -> (125.7627, 263.0375)
  line L69 (134.1267, 292.6862) -> (142.6772, 269.1939)
  line L70 (103.5314, 324.1175) -> (120.3669, 330.2451)
  line L71 (500, 900) -> (500, 0)
  line L72 (30, 900) -> (500, 900)
  line L73 (30, 0) -> (30, 900)
  line L74 (500, 0) -> (30, 0)
  circle C1 centre (45, 185) radius 1
  circle C2 centre (110, 152) radius 1
  circle C3 centre (170, 122) radius 1
  circle C4 centre (210, 102) radius 1
  circle C5 centre (170, 5) radius 1
  circle C6 centre (110, 5) radius 1
  circle C7 centre (45, 5) radius 1
  circle C8 centre (100, 60) radius 7.5
  circle C9 centre (210, 5) radius 1
  circle C10 centre (285, 5) radius 1
  circle C11 centre (330, 5) radius 1
  circle C12 centre (410, 5) radius 1
  circle C13 centre (470, 5) radius 1
  circle C14 centre (330, 75.5) radius 1
  circle C15 centre (285, 102) radius 1
  circle C16 centre (330, 122) radius 1
  circle C17 centre (400, 94.5) radius 1
  circle C18 centre (410, 164) radius 1
  circle C19 centre (459.921, 188.1491) radius 1
  circle C20 centre (199.5, 28.0698) radius 6
  circle C21 centre (350, 25) radius 7.5
  circle C22 centre (470.0076, 235) radius 1
  circle C23 centre (470.0076, 350) radius 1
  circle C24 centre (470, 435) radius 1
  circle C25 centre (470, 505) radius 1
  circle C26 centre (470, 560) radius 1
  circle C27 centre (450, 651) radius 1
  circle C28 centre (470, 716) radius 1
  circle C29 centre (470, 729) radius 1
  circle C30 centre (422, 846) radius 1
  circle C31 centre (492.7435, 816.5624) radius 1
  circle C32 centre (438.5624, 880.2435) radius 1
  circle C33 centre (40, 420) radius 2.25
  circle C34 centre (450, 515) radius 2.25
  circle C35 centre (420, 547.4) radius 6
  circle C36 centre (420, 572.4) radius 6
  circle C37 centre (420, 597.4) radius 6
  circle C38 centre (420, 622.4) radius 6
  circle C39 centre (120, 582.4) radius 6
  circle C40 centre (120, 607.4) radius 6
  circle C41 centre (120, 632.4) radius 6
  circle C42 centre (120, 557.4) radius 6
  circle C43 centre (249.9908, 235.1562) radius 6
  arc A1 centre (229.6708, 326.5962) radius 3.048 between (227.0311, 325.0722) and (227.0311, 328.1202)
  arc A2 centre (267.6711, 279.3522) radius 0.0635 clockwise from (267.7346, 279.3522) to (267.6076, 279.3522)
  arc A3 centre (267.6475, 279.3522) radius 0.0635 clockwise from (267.711, 279.3522) to (267.584, 279.3522)
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  point P2 (45, 185)
  point P3 (45, 185)
  point P11 (100, 60)
  point P12 (100, 60)
  point P27 (350, 25)
  point P28 (350, 25)
  point P47 (443, 643)
  point P49 (450, 515)
  point P50 (450, 515)
  point P1025 (97, 651)
  point P1105 (336.7469, 711.6223)
  point P1106 (336.7469, 711.6223)
  point P1107 (409, 734)
  point P1108 (409, 734)
  point P1109 (347, 819)
  point P1110 (347, 819)
  point P1111 (250, 859.5)
  point P1112 (250, 859.5)
  point P1113 (115, 890)
  point P1114 (115, 890)
  point P1115 (45, 890)
  point P1116 (45, 890)
  point P1117 (70, 759)
  point P1118 (70, 759)
  point P1119 (70, 743)
  point P1120 (70, 743)
  point P1121 (35, 759)
  point P1122 (35, 759)
  point P1123 (35, 743)
  point P1124 (35, 743)
  point P1125 (69.8745, 635.9997)
  point P1126 (69.8745, 635.9997)
  point P1127 (69.8745, 613.9997)
  point P1128 (69.8745, 613.9997)
  point P1129 (34.8745, 635.9997)
  point P1130 (34.8745, 635.9997)
  point P1131 (34.8745, 613.9997)
  point P1132 (34.8745, 613.9997)
  point P1133 (105.4372, 634.5)
  point P1134 (105.4372, 634.5)
  point P1135 (105.4372, 554.5)
  point P1136 (105.4372, 554.5)
  point P1137 (105.4372, 594.5)
  point P1138 (105.4372, 594.5)
  point P1139 (35, 540)
  point P1140 (35, 540)
  point P1141 (40, 445)
  point P1142 (40, 445)
  point P1143 (75, 460)
  point P1144 (75, 460)
  point P1145 (100, 460)
  point P1146 (100, 460)
  point P1148 (67, 369)
  point P1149 (67, 369)
  point P1150 (67, 350)
  point P1151 (67, 350)
  point P1152 (176.7629, 178.9842)
  point P1153 (176.7629, 178.9842)
  point P1154 (151.6461, 192.2903)
  point P1155 (151.6461, 192.2903)
  point P1156 (67, 235)
  point P1157 (67, 235)
  point P1158 (323.2371, 178.9842)
  point P1159 (323.2371, 178.9842)
  point P1160 (348.3539, 192.2903)
  point P1161 (348.3539, 192.2903)
  point P1162 (433, 235)
  point P1163 (433, 235)
  point P1164 (433, 369)
  point P1165 (433, 369)
  point P1166 (433, 350)
  point P1167 (433, 350)
  point P1168 (435.4453, 626.8042)
  point P1169 (435.4453, 626.8042)
  point P1170 (435.4453, 586.8042)
  point P1171 (435.4453, 586.8042)
  point P1172 (435.4453, 546.8042)
  point P1173 (435.4453, 546.8042)
  point P1174 (90, 514.0833)
  point P1175 (90, 514.0833)
  point P1177 (500, 900)
  point P1178 (30, 900)
  point P1179 (30, 0)
  point P1180 (500, 0)
  coincident P2 P3
  coincident P11 P12
  coincident P27 P28
  perpendicular L1 L2
  perpendicular L2 L3
  perpendicular L3 L4
  perpendicular L4 L5
  coincident L2 P47
  coincident P49 P50
  perpendicular L51 L54
  perpendicular L51 L52
  perpendicular L52 L53
  coincident P1025 L54
  perpendicular L55 L57
  perpendicular L55 L58
  perpendicular L58 L59
  perpendicular L57 L60
  perpendicular L56 L61
  perpendicular L56 L62
  perpendicular L64 L68
  perpendicular L68 L70
  perpendicular L66 L70
  perpendicular L64 L69
  perpendicular L63 L67
  perpendicular L63 L65
  coincident P1105 P1106
  coincident P1107 P1108
  coincident P1109 P1110
  coincident P1111 P1112
  coincident P1113 P1114
  coincident P1115 P1116
  coincident P1117 P1118
  coincident P1119 P1120
  coincident P1121 P1122
  coincident P1123 P1124
  coincident P1125 P1126
  coincident P1127 P1128
  coincident P1129 P1130
  coincident P1131 P1132
  coincident P1133 P1134
  coincident P1135 P1136
  coincident P1137 P1138
  coincident P1139 P1140
  coincident P1141 P1142
  coincident P1143 P1144
  coincident P1145 P1146
  coincident P1148 P1149
  coincident P1150 P1151
  coincident P1152 P1153
  coincident P1154 P1155
  coincident P1156 P1157
  coincident P1158 P1159
  coincident P1160 P1161
  coincident P1162 P1163
  coincident P1164 P1165
  coincident P1166 P1167
  coincident P1168 P1169
  coincident P1170 P1171
  coincident P1172 P1173
  coincident P1174 P1175
  vertical L71
  perpendicular L71 L72
  perpendicular L72 L73
  perpendicular L73 L74
  dimension "d1271" distance P1177 P1178 = 470
  dimension "d1272" distance P1179 P1180 = 470
extrude "Extrude225" add sketch "Top Runways" profile of L20 L75 L76 L77 along normal blind 41
chamfer "Chamfer22" distance 4.7 distance 41
extrude "Extrude226" add sketch "Top Runways" along normal blind 25
chamfer "Chamfer23" distance 2.8 distance 25
fillet "Fillet70" radius 1
extrude "Extrude227" new body sketch "Reload Flipper" profile of C1 C2 blind 4.8 from offset 3.2 bodies "Reload Load Coupling Bushing"
sketch "Final Sketch" plane through (0, 0, 0) normal (0, 0, 1) x axis (1, 0, 0)
  curve K1
  curve K2 (16.6295, -32.8917) -> (17.0352, -32.4352)
  curve K3 (38.3174, -2.664) -> (37.342, -2.7955)
  curve K4 (38.0277, -44.8705) -> (38.2161, -41.2226)
  curve K5 (23.3851, -37.6427) -> (25.5609, -34.9002)
  curve K6 (15.1625, -56.2307) -> (15.2719, -56.9091)
  curve K7 (17.9456, -43.4205) -> (16.9285, -43.5004)
  curve K8 (18.7819, -55.8368) -> (18.3879, -54.7152)
  curve K9 (38.6413, -47.5211) -> (38.4076, -47.4205)
  curve K10 (20.7481, -56.7126) -> (21.572, -56.8018)
  curve K11 (22.3268, -26.114) -> (21.0701, -27.0135)
  curve K12 (49.5147, -16.6251) -> (49.8549, -13.0537)
  curve K13 (39.7773, -30.1644) -> (40.7073, -28.6551)
  curve K14 (15.4477, -77.5467) -> (16.3737, -76.718)
  curve K15 (43.0789, -20.2886) -> (45.8383, -19.6367)
  curve K16 (27.0232, -25.0092) -> (27.1675, -24.233)
  curve K17 (46.9351, -14.1789) -> (48.1899, -15.747)
  curve K18 (13.6972, -53.5822) -> (14.454, -55.0374)
  line L1 (33.2868, -10.1695) -> (32.6745, -10.7398)
  curve K19 (37.0176, -29.5901) -> (37.2717, -30.602)
  curve K20 (18.6989, -37.9142) -> (17.7645, -38.2559)
  curve K21 (23.4514, -7.2997) -> (23.0007, -8.0934)
  curve K22 (8.1716, -73.3173) -> (10.4206, -73.6994)
  line L2 (10.1104, -39.4032) -> (10.061, -41.2781)
  curve K23 (41.1893, -34.1549) -> (40.4575, -34.5973)
  curve K24 (19.5572, -30.1859) -> (20.0572, -30.2953)
  curve K25 (23.0007, -8.0934) -> (22.465, -10.2926)
  curve K26 (10.9612, -40.8708) -> (11.336, -39.1158)
  curve K27 (45.5849, -26.2183) -> (45.0744, -26.0745)
  curve K28 (38.2685, -27.8933) -> (38.1877, -28.654)
  curve K29 (14.6672, -78.2274) -> (15.4477, -77.5467)
  curve K30 (36.3333, -28.0226) -> (36.6785, -28.612)
  curve K31 (37.3645, -30.9828) -> (37.7388, -31.4127)
  line L3 (42.5674, -32.5012) -> (43.2198, -32.3403)
  curve K32 (24.5659, -7.0068) -> (26.9431, -3.807)
  curve K33 (17.658, -44.2091) -> (18.5842, -40.0419)
  curve K34 (43.4908, -31.5091) -> (42.4973, -31.1678)
  curve K35 (37.7388, -31.4127) -> (38.4612, -31.8825)
  curve K36 (20.4729, -37.5873) -> (21.7746, -36.6354)
  curve K37 (17.7645, -38.2559) -> (16.7703, -38.6531)
  curve K38 (38.208, -47.2752) -> (38.4024, -45.8062)
  curve K39 (14.0939, -42.8861) -> (10.9612, -40.8708)
  curve K40 (20.0179, -29.7763) -> (20.4104, -29.0928)
  curve K41 (34.0744, -4.6843) -> (33.8696, -7.3581)
  line L4 (17.2868, -45.1682) -> (17.1954, -44.2091)
  curve K42 (22.5874, -56.2542) -> (22.112, -55.6407)
  curve K43 (19.4154, -29.9204) -> (19.5572, -30.1859)
  curve K44 (41.706, -22.4471) -> (43.0789, -20.2886)
  curve K45 (28.6582, -1.4295) -> (27.5651, -1.9654)
  curve K46 (12.5965, -48.4424) -> (12.1337, -45.8627)
  curve K47 (32.0024, -18.6106) -> (28.4263, -17.0319)
  curve K48 (27.4835, -3.1159) -> (28.2578, -2.5292)
  curve K49 (28.9333, -14.768) -> (31.2526, -15.2332)
  curve K50 (35.7464, -3.3778) -> (34.0744, -4.6843)
  curve K51 (11.9507, -48.1216) -> (12.7765, -51.312)
  line L5 (10.061, -41.2781) -> (10.5548, -42.0781)
  curve K52 (53.8123, -30.3192) -> (58.9716, -31.0424)
  curve K53 (33.6853, -28.4555) -> (33.3732, -28.9834)
  curve K54 (36.7498, -45.2477) -> (36.6666, -45.9447)
  curve K55 (21.2625, -57.3138) -> (20.7481, -56.7126)
  curve K56 (37.342, -2.7955) -> (35.7464, -3.3778)
  curve K57 (41.1368, -29.6224) -> (41.577, -33.3297)
  line L6 (32.6745, -10.7398) -> (32.7622, -11.8309)
  curve K58 (44.8448, -5.3153) -> (46.6404, -10.968)
  curve K59 (46.5191, -22.7754) -> (47.59, -18.2782)
  line L7 (38.8296, -1.1849) -> (38.4664, -1.4708)
  curve K60 (22.7899, -34.9536) -> (20.9047, -36.3136)
  curve K61 (23.3852, -56.4624) -> (22.6921, -56.3365)
  curve K62 (22.0025, -40.6372) -> (21.1052, -43.9445)
  curve K63 (15.924, -33.8843) -> (16.6295, -32.8917)
  curve K64 (41.577, -33.3297) -> (41.1893, -34.1549)
  curve K65 (42.2502, -35.2132) -> (42.471, -33.1627)
  curve K66 (11.4789, -36.1246) -> (10.4887, -36.8669)
  curve K67 (44.4273, -27.2138) -> (45.0957, -27.0153)
  curve K68 (10.5548, -42.0781) -> (11.3521, -45.1948)
  curve K69 (32.977, -26.6169) -> (33.963, -26.8667)
  curve K70 (33.8402, -10.5162) -> (34.4989, -7.4981)
  curve K71 (41.906, -19.3355) -> (40.3839, -21.0243)
  curve K72 (33.963, -26.8667) -> (34.4612, -27.5877)
  curve K73 (26.9431, -3.807) -> (27.4835, -3.1159)
  curve K74 (17.0352, -32.4352) -> (19.4154, -29.9204)
  curve K75 (28.4263, -17.0319) -> (28.9333, -14.768)
  curve K76 (34.2642, -30.5785) -> (36.3333, -28.0226)
  curve K77 (38.2028, -47.6502) -> (38.6413, -47.5211)
  curve K78 (31.2526, -15.2332) -> (32.2901, -15.4356)
  line L8 (33.8696, -7.3581) -> (33.8991, -9.5993)
  curve K79 (43.725, -26.0681) -> (41.5214, -25.1361)
  curve K80 (37.1178, -50.8947) -> (36.6095, -51.1433)
  curve K81 (45.8383, -19.6367) -> (45.9702, -21.145)
  curve K82 (27.5651, -1.9654) -> (23.4514, -7.2997)
  curve K83 (36.6785, -28.612) -> (37.0176, -29.5901)
  line L9 (42.471, -33.1627) -> (42.5674, -32.5012)
  curve K84 (37.2717, -30.602) -> (37.3645, -30.9828)
  curve K85 (25.7169, -18.658) -> (27.6653, -20.2696)
  curve K86 (33.3781, -30.4838) -> (34.2642, -30.5785)
  curve K87
  curve K88 (35.4237, -0.0041) -> (31.3671, -0.3731)
  curve K89 (40.3766, -35.2175) -> (40.5621, -35.8836)
  curve K90 (32.6284, -18.6136) -> (32.0024, -18.6106)
  curve K91 (45.0744, -26.0745) -> (46.1483, -23.9294)
  curve K92 (34.4612, -27.5877) -> (33.6853, -28.4555)
  curve K93 (44.2795, -12.3238) -> (44.0971, -14.1744)
  curve K94 (37.4121, -28.001) -> (36.1087, -26.4821)
  curve K95 (36.9016, -52.466) -> (37.1123, -52.9905)
  curve K96 (40.4575, -34.5973) -> (40.3766, -35.2175)
  curve K97 (45.2854, -13.6385) -> (44.7602, -10.6832)
  curve K98 (47.3961, -9.9568) -> (46.8669, -7.6304)
  curve K99 (50.6604, -36.1402) -> (55.9694, -36.6023)
  curve K100 (36.6806, -51.8821) -> (36.9016, -52.466)
  curve K101 (38.1877, -28.654) -> (37.4121, -28.001)
  curve K102 (42.9848, -27.2096) -> (44.4273, -27.2138)
  curve K103 (25.8326, -17.5983) -> (25.4532, -16.9285)
  curve K104 (49.8549, -13.0537) -> (48.398, -12.7169)
  curve K105 (12.6564, -43.2122) -> (14.6241, -43.8707)
  curve K106 (73.1231, -26.8024) -> (74.1359, -26.564)
  curve K107 (14.6932, -43.0445) -> (14.0939, -42.8861)
  curve K108 (37.8808, -47.5794) -> (38.2028, -47.6502)
  curve K109 (44.0833, -25.826) -> (43.725, -26.0681)
  curve K110 (47.736, -17.6417) -> (46.4158, -17.7671)
  curve K111 (45.5343, -14.1788) -> (45.2854, -13.6385)
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extrude "Extrude229" new body sketch "BackBox" along normal blind 2 bodies "Serviceman Outline"
extrude "Extrude230" new body sketch "BackBox" along normal blind 2 bodies "Serviceman Skin"
extrude "Extrude231" new body sketch "BackBox" along normal blind 2 bodies "Serviceman Shirt and Hair"
extrude "Extrude232" new body sketch "BackBox" along normal blind 2 bodies "Serviceman Pants and Glasses"
scale "Scale12" ScaleX 2 ScaleY 2
move "Move20"
scale "Scale13" ScaleX 2 ScaleY 2
move "Move21"
scale "Scale14" ScaleX 2 ScaleY 2
move "Move22"
scale "Scale15" ScaleX 2 ScaleY 2
move "Move23"
sketch "Bumper Flash" plane through (0, 0, 0) normal (0, 0, 1) x axis (1, 0, 0)
  line L1 (161.6908, 727.1955) -> (150, 750)
  line L2 (185.3553, 735.3553) -> (161.6908, 727.1955)
  line L3 (178.224, 711.6908) -> (185.3553, 735.3553)
  line L4 (200, 700) -> (178.224, 711.6908)
  line L5 (178.224, 688.3092) -> (200, 700)
  line L6 (185.3553, 664.6447) -> (178.224, 688.3092)
  line L7 (161.6908, 671.776) -> (185.3553, 664.6447)
  line L8 (150, 650) -> (161.6908, 671.776)
  line L9 (138.3092, 671.776) -> (150, 650)
  line L10 (114.6447, 664.6447) -> (138.3092, 671.776)
  line L11 (114.6447, 664.6447) -> (121.776, 688.3092)
  line L12 (100, 700) -> (121.776, 688.3092)
  line L13 (121.776, 711.6908) -> (100, 700)
  line L14 (114.6447, 735.3553) -> (121.776, 711.6908)
  line L15 (138.3092, 728.224) -> (114.6447, 735.3553)
  line L16 (138.3092, 728.224) -> (150, 750)
  line L17 (210, 760) -> (90, 760)
  line L18 (210, 640) -> (210, 760)
  line L19 (90, 640) -> (210, 640)
  line L20 (90, 760) -> (90, 640)
  horizontal L17
  perpendicular L17 L18
  perpendicular L18 L19
  perpendicular L17 L20
extrude "Extrude233" new body sketch "Bumper Flash" along normal blind 2.4 bodies "Bumper Flash"
fillet "Fillet71" radius 2
fillet "Fillet72" radius 2
fillet "Fillet73" radius 2
extrude "Extrude234" new body sketch "BackBox" along normal blind 2 bodies "Start"
extrude "Extrude235" cut sketch "BackBox" along normal blind 2 bodies "Start (1)"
